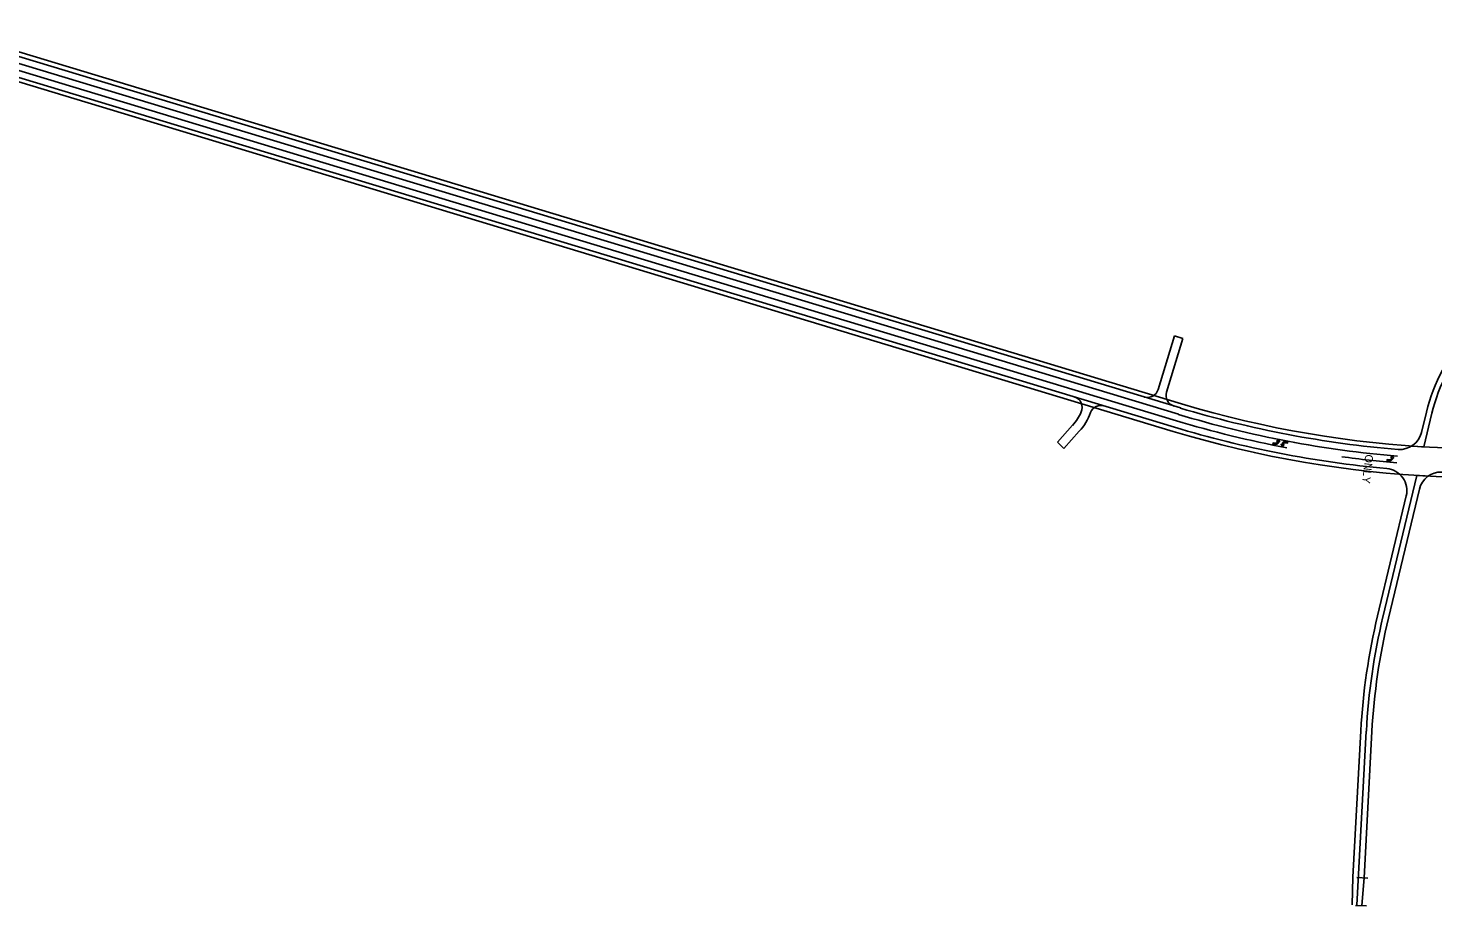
# Model space of a CAD drawing. Extents: x 979036 to 996074, y 1836928 to 1845163.
# Drawn here: x 981565 to 984093, y 1836928 to 1838507 of the extents above; entities that cross this region are included whole.
import ezdxf

# ---------------------------------------------------------------- set-up
doc = ezdxf.new("R2010")
doc.units = 0
for name, color, linetype in [('R_Proposed Road', 7, 'Continuous'), ('STRIPE_White Stopbar', 7, 'Continuous'), ('STRIPE_White Turn Arrow', 7, 'Continuous'), ('STRIPE_White_6in', 7, 'Continuous'), ('STRIPE_White_ONLY', 7, 'Continuous'), ('STRIPE_Yellow Dbl 6in', 7, 'Continuous'), ('STRIPE_Yellow_10_30 SKIP', 7, 'Continuous')]:
    doc.layers.add(name, color=color, linetype=linetype)

msp = doc.modelspace()

# ---------------------------------------------------------------- linework, layer by layer
at = {"layer": 'R_Proposed Road'}
for p, q in [((981406.9, 1838507.1), (983640.8, 1837831.3)), ((981391.8, 1838457.4), (983625.8, 1837781.5)), ((983627.8, 1837953.6), (983598.4, 1837856.7)), ((983643, 1837948.6), (983613.7, 1837852)), ((983627.8, 1837953.6), (983643, 1837948.6)), ((983417.2, 1837761.8), (983444.6, 1837792.4)), ((983429, 1837751), (983456.5, 1837781.7)), ((983417.2, 1837761.8), (983429, 1837751)), ((983949.1, 1836979.4), (983963.3, 1837242.6)), ((983969.1, 1836978.4), (983983.2, 1837241.5)), ((983949.1, 1836979.4), (983948, 1836929.4)), ((983956, 1836978.6), (983976, 1836977.6)), ((983965, 1836928.5), (983969.1, 1836978.4)), ((983953.7, 1836928.6), (983973.7, 1836927.7))]:
    msp.add_line(p, q, dxfattribs=at)
for centre, radius, start, end in [((983579.3, 1837862.5), 20, 253.1679, 343.1679), ((983441.9, 1837824.6), 20, 336.1594, 73.1679), ((983632.9, 1837846.2), 20, 163.1679, 253.1679), ((984186.3, 1839634.4), 1883.9, 253.1679, 281.6644), ((983376.1, 1837853.7), 92, 318.1679, 336.1594), ((983376.1, 1837853.7), 108, 318.1679, 339.2323), ((983495.7, 1837808.3), 20, 73.1679, 159.2323), ((984186.3, 1839634.4), 1935.9, 253.1679, 281.6644), ((985117.5, 1837180.4), 1155.9, 166.5199, 176.9167), ((985117.5, 1837180.4), 1135.9, 166.5199, 176.9167)]:
    msp.add_arc(centre, radius, start, end, dxfattribs=at)
at = {"layer": 'STRIPE_White Stopbar'}
for p, q in [((984076.6, 1837753.8), (984055.1, 1837755.2)), ((984064.3, 1837702.4), (984085, 1837701.2))]:
    msp.add_line(p, q, dxfattribs=at)
at = {"layer": 'STRIPE_White Turn Arrow'}
for points in [[(983811.8, 1837763.6), (983814.6, 1837766.8), (983817.1, 1837763.2), (983815.4, 1837763.3), (983815.3, 1837762.7), (983815.2, 1837762.1), (983814.9, 1837761.4), (983814.4, 1837760.5), (983813.9, 1837759.8), (983813.3, 1837759.3), (983812.5, 1837758.7), (983811.8, 1837758.4), (983811, 1837758.1), (983810, 1837758), (983809, 1837758), (983805.2, 1837758.7), (983805.5, 1837760.6), (983809.1, 1837760.1), (983809.8, 1837760), (983810.5, 1837760.1), (983811.3, 1837760.4), (983812.1, 1837760.8), (983812.3, 1837761.1), (983812.8, 1837761.6), (983813.1, 1837762.4), (983813.4, 1837763.1), (983813.4, 1837763.5)], [(983825.2, 1837757.6), (983822.4, 1837754.3), (983819.9, 1837757.9), (983821.6, 1837757.8), (983821.7, 1837758.4), (983821.8, 1837759), (983822.1, 1837759.8), (983822.6, 1837760.6), (983823.1, 1837761.3), (983823.8, 1837761.8), (983824.5, 1837762.4), (983825.2, 1837762.7), (983826, 1837763), (983827, 1837763.1), (983828, 1837763.1), (983831.9, 1837762.4), (983831.5, 1837760.4), (983828, 1837761), (983827.3, 1837761.1), (983826.5, 1837761), (983825.7, 1837760.7), (983825, 1837760.3), (983824.7, 1837760), (983824.2, 1837759.5), (983823.9, 1837758.7), (983823.6, 1837758), (983823.6, 1837757.7)], [(984017.1, 1837734), (984020, 1837737.3), (984022.4, 1837733.8), (984020.8, 1837733.8), (984020.7, 1837733.2), (984020.6, 1837732.6), (984020.3, 1837731.8), (984019.8, 1837731), (984019.3, 1837730.3), (984018.7, 1837729.8), (984017.9, 1837729.2), (984017.2, 1837728.9), (984016.4, 1837728.6), (984015.4, 1837728.5), (984014.4, 1837728.4), (984010.6, 1837729.1), (984010.9, 1837731), (984014.4, 1837730.5), (984015.1, 1837730.5), (984015.9, 1837730.6), (984016.7, 1837730.8), (984017.4, 1837731.3), (984017.7, 1837731.6), (984018.2, 1837732.1), (984018.5, 1837732.8), (984018.7, 1837733.6), (984018.8, 1837733.9)]]:
    msp.add_lwpolyline(points, close=True, dxfattribs=at)
at = {"layer": 'STRIPE_White_6in'}
for p, q in [((981404.5, 1838499.5), (983638.5, 1837823.6)), ((981394.1, 1838465), (983628.1, 1837789.2)), ((984081.3, 1837816.3), (984072.5, 1837779.6)), ((984012.9, 1837445.2), (984068.6, 1837677.5)), ((983993.4, 1837449.9), (984045.1, 1837665.5)), ((983949.1, 1836979.4), (983963.3, 1837242.6)), ((983969.1, 1836978.4), (983983.2, 1837241.5)), ((983949.1, 1836979.4), (983948, 1836929.4)), ((983965, 1836928.5), (983969.1, 1836978.4))]:
    msp.add_line(p, q, dxfattribs=at)
for centre, radius, start, end in [((984369.6, 1837747.2), 296.5, 135.2714, 166.5199), ((984186.3, 1839634.4), 1891.9, 253.1679, 265.2678), ((984186.3, 1839634.4), 1927.9, 253.1679, 264.7484), ((984033.6, 1837788.9), 40, 265.2678, 346.5199), ((984186.3, 1839634.4), 1915.9, 262.2772, 265.2678), ((984006.2, 1837674.8), 40, 346.5199, 84.7484), ((984107.5, 1837668.2), 40, 87.7026, 166.5199), ((985117.5, 1837180.4), 1155.9, 166.5199, 176.9167), ((985117.5, 1837180.4), 1135.9, 166.5199, 176.9167)]:
    msp.add_arc(centre, radius, start, end, dxfattribs=at)
at = {"layer": 'STRIPE_Yellow Dbl 6in'}
for p, q in [((984091, 1837814), (984076.6, 1837753.8)), ((984003.1, 1837447.5), (984064.3, 1837702.4)), ((983956.4, 1836929), (983973.2, 1837242))]:
    msp.add_line(p, q, dxfattribs=at)
for centre, radius, start, end in [((984369.6, 1837747.2), 286.5, 135.2714, 166.5199), ((984186.3, 1839634.4), 1903.9, 259.2787, 265.2678), ((985117.5, 1837180.4), 1145.9, 166.5199, 176.9167)]:
    msp.add_arc(centre, radius, start, end, dxfattribs=at)
at = {"layer": 'STRIPE_Yellow_10_30 SKIP'}
for p, q in [((981401.1, 1838488), (983635, 1837812.2)), ((981401.1, 1838488), (983635, 1837812.2)), ((983631.6, 1837800.7), (981397.6, 1838476.5)), ((981397.6, 1838476.5), (983631.6, 1837800.7))]:
    msp.add_line(p, q, dxfattribs=at)
for radius, end in [(1903.9, 259.2787), (1903.9, 259.2787), (1915.9, 259.2866), (1915.9, 259.2866)]:
    msp.add_arc((984186.3, 1839634.4), radius, 253.1679, end, dxfattribs=at)

# ---------------------------------------------------------------- texts
at = {"layer": 'STRIPE_White_ONLY'}
msp.add_text('ONLY', height=14.4, rotation=263.6335, dxfattribs=at).set_placement((983971.4, 1837740.6))

doc.saveas('drawing.dxf')
